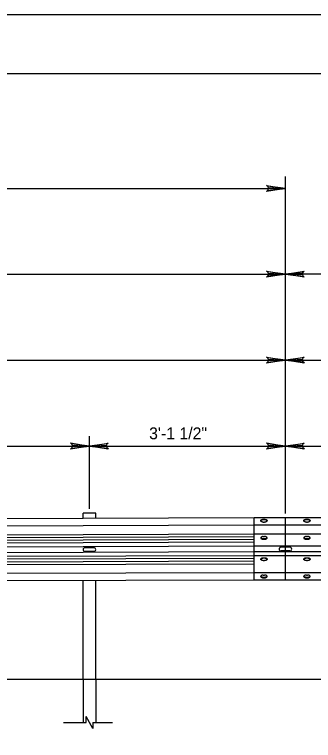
# Model space of a CAD drawing. Extents: x 637628 to 640188, y 298266 to 300751.
# Drawn here: x 639616.3 to 639692, y 299269.8 to 299453.6 of the extents above; entities that cross this region are included whole.
import ezdxf

# ---------------------------------------------------------------- set-up
doc = ezdxf.new("R2010")
doc.units = 0
for name, color, linetype in [('1', 7, 'Continuous'), ('2', 7, 'Continuous'), ('PLT-BNDY', 7, 'Continuous'), ('S-ABUT-CONC', 7, 'Continuous'), ('S-ANNO-CELL', 7, 'Continuous')]:
    doc.layers.add(name, color=color, linetype=linetype)

msp = doc.modelspace()

# ---------------------------------------------------------------- linework, layer by layer
at = {"layer": '1'}
msp.add_line((639676.99, 299310.39), (639676.99, 299326.12), dxfattribs=at)
msp.add_lwpolyline([(639945.52, 298874.58), (639945.52, 299438.55), (639159.55, 299438.55), (639159.55, 298874.58), (639945.52, 298874.58), (639945.52, 298900.93), (639745.53, 298900.93), (639745.53, 298965.61), (639945.52, 298965.61), (639945.52, 298994.57), (639745.53, 298994.57), (639745.53, 298874.58), (639824.33, 298874.58), (639824.33, 298900.93), (639824.33, 298874.58), (639901.33, 298874.58), (639901.33, 298900.93), (639901.33, 298888.62), (639945.52, 298888.62)], dxfattribs=at)
at = {"layer": '2'}
for points in [[(639680.4, 299410.12), (639680.57, 299409.79), (639684.94, 299409.55), (639680.4, 299410.12), (639680.17, 299410.32), (639684.94, 299409.55), (639680.58, 299409.33), (639680.42, 299409.01), (639684.94, 299409.55), (639680.17, 299408.79), (639680.42, 299409.01)], [(639680.4, 299388.41), (639680.57, 299388.08), (639684.94, 299387.84), (639680.4, 299388.41), (639680.17, 299388.61), (639684.94, 299387.84), (639680.58, 299387.62), (639680.42, 299387.3), (639684.94, 299387.84), (639680.17, 299387.08), (639680.42, 299387.3)], [(639689.48, 299387.27), (639689.31, 299387.6), (639684.94, 299387.84), (639689.48, 299387.27), (639689.72, 299387.07), (639684.94, 299387.84), (639689.31, 299388.05), (639689.47, 299388.38), (639684.94, 299387.84), (639689.72, 299388.6), (639689.47, 299388.38)], [(639680.4, 299366.65), (639680.57, 299366.32), (639684.94, 299366.09), (639680.4, 299366.65), (639680.17, 299366.85), (639684.94, 299366.09), (639680.58, 299365.87), (639680.42, 299365.54), (639684.94, 299366.09), (639680.17, 299365.32), (639680.42, 299365.54)], [(639689.48, 299365.52), (639689.31, 299365.85), (639684.94, 299366.09), (639689.48, 299365.52), (639689.72, 299365.32), (639684.94, 299366.09), (639689.31, 299366.3), (639689.47, 299366.63), (639684.94, 299366.09), (639689.72, 299366.85), (639689.47, 299366.63)], [(639630.74, 299344.9), (639630.91, 299344.57), (639635.28, 299344.33), (639630.74, 299344.9), (639630.51, 299345.1), (639635.28, 299344.33), (639630.92, 299344.12), (639630.76, 299343.79), (639635.28, 299344.33), (639630.51, 299343.57), (639630.76, 299343.79)], [(639639.82, 299343.76), (639639.65, 299344.09), (639635.28, 299344.33), (639639.82, 299343.76), (639640.06, 299343.56), (639635.28, 299344.33), (639639.65, 299344.55), (639639.81, 299344.87), (639635.28, 299344.33), (639640.06, 299345.09), (639639.81, 299344.87)], [(639680.4, 299344.9), (639680.57, 299344.57), (639684.94, 299344.33), (639680.4, 299344.9), (639680.17, 299345.1), (639684.94, 299344.33), (639680.58, 299344.12), (639680.42, 299343.79), (639684.94, 299344.33), (639680.17, 299343.57), (639680.42, 299343.79)], [(639689.48, 299343.76), (639689.31, 299344.09), (639684.94, 299344.33), (639689.48, 299343.76), (639689.72, 299343.56), (639684.94, 299344.33), (639689.31, 299344.55), (639689.47, 299344.87), (639684.94, 299344.33), (639689.72, 299345.09), (639689.47, 299344.87)]]:
    msp.add_lwpolyline(points, dxfattribs=at)
at = {"layer": 'PLT-BNDY'}
msp.add_lwpolyline([(639119.52, 299453.58), (639960.52, 299453.58), (639960.52, 298859.58), (639119.52, 298859.58)], close=True, dxfattribs=at)
at = {"layer": 'S-ABUT-CONC'}
for p, q in [((639684.94, 299327.27), (639684.94, 299412.56)), ((639287.66, 299409.55), (639684.94, 299409.55)), ((639486.3, 299387.84), (639684.94, 299387.84)), ((639899.46, 299387.84), (639684.94, 299387.84)), ((639486.3, 299366.09), (639684.94, 299366.09)), ((639684.94, 299366.09), (639833.71, 299366.09)), ((639635.28, 299328.4), (639635.28, 299346.82)), ((639535.96, 299344.33), (639635.28, 299344.33)), ((639635.28, 299344.33), (639684.94, 299344.33)), ((639684.94, 299344.33), (639734.6, 299344.33))]:
    msp.add_line(p, q, dxfattribs=at)
at = {"layer": 'S-ANNO-CELL'}
for p, q in [((639676.99, 299326.12), (639494.26, 299325.48)), ((639636.87, 299327.37), (639633.69, 299327.37)), ((639633.69, 299325.97), (639633.69, 299327.37)), ((639636.87, 299325.98), (639636.87, 299327.37)), ((639895.3, 299326.12), (639676.99, 299326.12)), ((639684.94, 299310.52), (639684.94, 299326.12)), ((639676.99, 299324.27), (639494.26, 299323.63)), ((639825.97, 299324.27), (639676.99, 299324.27)), ((639679.33, 299325.77), (639679.65, 299325.77)), ((639679.33, 299325.66), (639679.33, 299325.77)), ((639679.65, 299325.66), (639679.33, 299325.66)), ((639679.33, 299325.06), (639679.65, 299325.06)), ((639679.65, 299325.66), (639679.65, 299325.77)), ((639690.24, 299325.77), (639690.56, 299325.77)), ((639690.24, 299325.66), (639690.24, 299325.77)), ((639690.56, 299325.66), (639690.24, 299325.66)), ((639690.24, 299325.06), (639690.56, 299325.06)), ((639690.56, 299325.66), (639690.56, 299325.77)), ((639676.99, 299322.01), (639494.26, 299321.37)), ((639676.99, 299321.32), (639494.26, 299320.68)), ((639676.99, 299320.63), (639494.26, 299320)), ((639825.97, 299322.01), (639676.99, 299322.01)), ((639679.33, 299321.42), (639679.65, 299321.42)), ((639679.33, 299320.82), (639679.33, 299320.71)), ((639679.65, 299320.82), (639679.33, 299320.82)), ((639679.33, 299320.71), (639679.65, 299320.71)), ((639679.65, 299320.82), (639679.65, 299320.71)), ((639690.24, 299321.42), (639690.56, 299321.42)), ((639690.24, 299320.82), (639690.24, 299320.71)), ((639690.56, 299320.82), (639690.24, 299320.82)), ((639690.24, 299320.71), (639690.56, 299320.71)), ((639690.56, 299320.82), (639690.56, 299320.71)), ((639676.99, 299319.95), (639494.26, 299319.31)), ((639676.99, 299318.95), (639494.26, 299318.31)), ((639825.97, 299318.95), (639676.99, 299318.95)), ((639684.94, 299318.73), (639683.83, 299318.73)), ((639686.06, 299318.73), (639684.94, 299318.73)), ((639676.99, 299317.55), (639494.26, 299316.91)), ((639635.28, 299318.58), (639634.17, 299318.58)), ((639635.28, 299317.63), (639634.17, 299317.63)), ((639636.4, 299318.58), (639635.28, 299318.58)), ((639636.4, 299317.63), (639635.28, 299317.63)), ((639825.97, 299317.55), (639676.99, 299317.55)), ((639684.94, 299317.77), (639683.83, 299317.77)), ((639686.06, 299317.77), (639684.94, 299317.77)), ((639676.99, 299316.56), (639494.26, 299315.95)), ((639676.99, 299315.87), (639494.26, 299315.23)), ((639676.99, 299315.14), (639494.26, 299314.5)), ((639825.97, 299316.56), (639676.99, 299316.56)), ((639679.33, 299316.02), (639679.65, 299316.02)), ((639679.33, 299315.91), (639679.33, 299316.02)), ((639679.65, 299315.91), (639679.33, 299315.91)), ((639679.33, 299315.31), (639679.65, 299315.31)), ((639679.65, 299315.91), (639679.65, 299316.02)), ((639690.24, 299316.02), (639690.56, 299316.02)), ((639690.24, 299315.91), (639690.24, 299316.02)), ((639690.56, 299315.91), (639690.24, 299315.91)), ((639690.24, 299315.31), (639690.56, 299315.31)), ((639690.56, 299315.91), (639690.56, 299316.02)), ((639676.99, 299314.45), (639494.26, 299313.82)), ((639676.99, 299312.24), (639494.26, 299311.6)), ((639825.97, 299312.24), (639676.99, 299312.24)), ((639679.33, 299311.67), (639679.65, 299311.67)), ((639690.24, 299311.67), (639690.56, 299311.67)), ((639676.99, 299310.39), (639494.26, 299309.75)), ((639633.69, 299285.33), (639633.69, 299310.24)), ((639636.87, 299285.33), (639636.87, 299310.25)), ((639825.97, 299310.39), (639676.99, 299310.39)), ((639679.33, 299311.07), (639679.33, 299310.96)), ((639679.65, 299311.07), (639679.33, 299311.07)), ((639679.33, 299310.96), (639679.65, 299310.96)), ((639679.65, 299311.07), (639679.65, 299310.96)), ((639690.24, 299311.07), (639690.24, 299310.96)), ((639690.56, 299311.07), (639690.24, 299311.07)), ((639690.24, 299310.96), (639690.56, 299310.96)), ((639690.56, 299311.07), (639690.56, 299310.96)), ((639581.11, 299285.33), (639895.3, 299285.33)), ((639633.69, 299285.33), (639633.69, 299274.31)), ((639636.87, 299285.33), (639636.87, 299274.31)), ((639634.46, 299274.31), (639634.46, 299275.81)), ((639636.1, 299272.81), (639634.46, 299275.81)), ((639628.69, 299274.31), (639632.92, 299274.31)), ((639629.46, 299274.31), (639634.46, 299274.31)), ((639636.1, 299274.31), (639636.1, 299272.81)), ((639636.1, 299274.31), (639641.1, 299274.31))]:
    msp.add_line(p, q, dxfattribs=at)
for points in [[(639679.33, 299325.06), (639679.22, 299325.07), (639679.11, 299325.08), (639679.01, 299325.11), (639678.92, 299325.15), (639678.84, 299325.19), (639678.78, 299325.24), (639678.73, 299325.3), (639678.7, 299325.36), (639678.69, 299325.42), (639678.7, 299325.48), (639678.73, 299325.54), (639678.78, 299325.6), (639678.84, 299325.65), (639678.92, 299325.69), (639679.01, 299325.73), (639679.11, 299325.75), (639679.22, 299325.77), (639679.33, 299325.77)], [(639679.33, 299325.66), (639679.22, 299325.66), (639679.11, 299325.64), (639679.01, 299325.62), (639678.92, 299325.58), (639678.84, 299325.54), (639678.78, 299325.49), (639678.73, 299325.43), (639678.7, 299325.37), (639678.7, 299325.36)], [(639679.65, 299325.77), (639679.76, 299325.77), (639679.86, 299325.75), (639679.96, 299325.73), (639680.05, 299325.69), (639680.13, 299325.65), (639680.2, 299325.6), (639680.24, 299325.54), (639680.27, 299325.48), (639680.28, 299325.42), (639680.27, 299325.36), (639680.24, 299325.3), (639680.2, 299325.24), (639680.13, 299325.19), (639680.05, 299325.15), (639679.96, 299325.11), (639679.86, 299325.08), (639679.76, 299325.07), (639679.65, 299325.06)], [(639680.27, 299325.36), (639680.27, 299325.37), (639680.24, 299325.43), (639680.2, 299325.49), (639680.13, 299325.54), (639680.05, 299325.58), (639679.96, 299325.62), (639679.86, 299325.64), (639679.76, 299325.66), (639679.65, 299325.66)], [(639690.24, 299325.06), (639690.13, 299325.07), (639690.02, 299325.08), (639689.92, 299325.11), (639689.83, 299325.15), (639689.75, 299325.19), (639689.69, 299325.24), (639689.64, 299325.3), (639689.61, 299325.36), (639689.6, 299325.42), (639689.61, 299325.48), (639689.64, 299325.54), (639689.69, 299325.6), (639689.75, 299325.65), (639689.83, 299325.69), (639689.92, 299325.73), (639690.02, 299325.75), (639690.13, 299325.77), (639690.24, 299325.77)], [(639690.24, 299325.66), (639690.13, 299325.66), (639690.02, 299325.64), (639689.92, 299325.62), (639689.83, 299325.58), (639689.75, 299325.54), (639689.69, 299325.49), (639689.64, 299325.43), (639689.61, 299325.37), (639689.61, 299325.36)], [(639690.56, 299325.77), (639690.67, 299325.77), (639690.78, 299325.75), (639690.88, 299325.73), (639690.97, 299325.69), (639691.05, 299325.65), (639691.11, 299325.6), (639691.16, 299325.54), (639691.19, 299325.48), (639691.2, 299325.42), (639691.19, 299325.36), (639691.16, 299325.3), (639691.11, 299325.24), (639691.05, 299325.19), (639690.97, 299325.15), (639690.88, 299325.11), (639690.78, 299325.08), (639690.67, 299325.07), (639690.56, 299325.06)], [(639691.19, 299325.36), (639691.19, 299325.37), (639691.16, 299325.43), (639691.11, 299325.49), (639691.05, 299325.54), (639690.97, 299325.58), (639690.88, 299325.62), (639690.78, 299325.64), (639690.67, 299325.66), (639690.56, 299325.66)], [(639679.33, 299321.42), (639679.22, 299321.42), (639679.11, 299321.4), (639679.01, 299321.37), (639678.92, 299321.34), (639678.84, 299321.29), (639678.78, 299321.24), (639678.73, 299321.19), (639678.7, 299321.13), (639678.69, 299321.06), (639678.7, 299321), (639678.73, 299320.94), (639678.78, 299320.89), (639678.84, 299320.84), (639678.92, 299320.79), (639679.01, 299320.76), (639679.11, 299320.73), (639679.22, 299320.71), (639679.33, 299320.71)], [(639679.33, 299320.82), (639679.22, 299320.82), (639679.11, 299320.84), (639679.01, 299320.87), (639678.92, 299320.9), (639678.84, 299320.95), (639678.78, 299321), (639678.73, 299321.05), (639678.7, 299321.11), (639678.7, 299321.12)], [(639679.65, 299320.71), (639679.76, 299320.71), (639679.86, 299320.73), (639679.96, 299320.76), (639680.05, 299320.79), (639680.13, 299320.84), (639680.2, 299320.89), (639680.24, 299320.94), (639680.27, 299321), (639680.28, 299321.06), (639680.27, 299321.13), (639680.24, 299321.19), (639680.2, 299321.24), (639680.13, 299321.29), (639680.05, 299321.34), (639679.96, 299321.37), (639679.86, 299321.4), (639679.76, 299321.42), (639679.65, 299321.42)], [(639680.27, 299321.12), (639680.27, 299321.11), (639680.24, 299321.05), (639680.2, 299321), (639680.13, 299320.95), (639680.05, 299320.9), (639679.96, 299320.87), (639679.86, 299320.84), (639679.76, 299320.82), (639679.65, 299320.82)], [(639690.24, 299321.42), (639690.13, 299321.42), (639690.02, 299321.4), (639689.92, 299321.37), (639689.83, 299321.34), (639689.75, 299321.29), (639689.69, 299321.24), (639689.64, 299321.19), (639689.61, 299321.13), (639689.6, 299321.06), (639689.61, 299321), (639689.64, 299320.94), (639689.69, 299320.89), (639689.75, 299320.84), (639689.83, 299320.79), (639689.92, 299320.76), (639690.02, 299320.73), (639690.13, 299320.71), (639690.24, 299320.71)], [(639690.24, 299320.82), (639690.13, 299320.82), (639690.02, 299320.84), (639689.92, 299320.87), (639689.83, 299320.9), (639689.75, 299320.95), (639689.69, 299321), (639689.64, 299321.05), (639689.61, 299321.11), (639689.61, 299321.12)], [(639690.56, 299320.71), (639690.67, 299320.71), (639690.78, 299320.73), (639690.88, 299320.76), (639690.97, 299320.79), (639691.05, 299320.84), (639691.11, 299320.89), (639691.16, 299320.94), (639691.19, 299321), (639691.2, 299321.06), (639691.19, 299321.13), (639691.16, 299321.19), (639691.11, 299321.24), (639691.05, 299321.29), (639690.97, 299321.34), (639690.88, 299321.37), (639690.78, 299321.4), (639690.67, 299321.42), (639690.56, 299321.42)], [(639691.19, 299321.12), (639691.19, 299321.11), (639691.16, 299321.05), (639691.11, 299321), (639691.05, 299320.95), (639690.97, 299320.9), (639690.88, 299320.87), (639690.78, 299320.84), (639690.67, 299320.82), (639690.56, 299320.82)], [(639679.33, 299315.31), (639679.22, 299315.32), (639679.11, 299315.33), (639679.01, 299315.36), (639678.92, 299315.4), (639678.84, 299315.44), (639678.78, 299315.49), (639678.73, 299315.55), (639678.7, 299315.61), (639678.69, 299315.67), (639678.7, 299315.73), (639678.73, 299315.79), (639678.78, 299315.85), (639678.84, 299315.9), (639678.92, 299315.94), (639679.01, 299315.98), (639679.11, 299316), (639679.22, 299316.02), (639679.33, 299316.02)], [(639679.33, 299315.91), (639679.22, 299315.91), (639679.11, 299315.89), (639679.01, 299315.87), (639678.92, 299315.83), (639678.84, 299315.79), (639678.78, 299315.74), (639678.73, 299315.68), (639678.7, 299315.62), (639678.7, 299315.61)], [(639679.65, 299316.02), (639679.76, 299316.02), (639679.86, 299316), (639679.96, 299315.98), (639680.05, 299315.94), (639680.13, 299315.9), (639680.2, 299315.85), (639680.24, 299315.79), (639680.27, 299315.73), (639680.28, 299315.67), (639680.27, 299315.61), (639680.24, 299315.55), (639680.2, 299315.49), (639680.13, 299315.44), (639680.05, 299315.4), (639679.96, 299315.36), (639679.86, 299315.33), (639679.76, 299315.32), (639679.65, 299315.31)], [(639680.27, 299315.61), (639680.27, 299315.62), (639680.24, 299315.68), (639680.2, 299315.74), (639680.13, 299315.79), (639680.05, 299315.83), (639679.96, 299315.87), (639679.86, 299315.89), (639679.76, 299315.91), (639679.65, 299315.91)], [(639690.24, 299315.31), (639690.13, 299315.32), (639690.02, 299315.33), (639689.92, 299315.36), (639689.83, 299315.4), (639689.75, 299315.44), (639689.69, 299315.49), (639689.64, 299315.55), (639689.61, 299315.61), (639689.6, 299315.67), (639689.61, 299315.73), (639689.64, 299315.79), (639689.69, 299315.85), (639689.75, 299315.9), (639689.83, 299315.94), (639689.92, 299315.98), (639690.02, 299316), (639690.13, 299316.02), (639690.24, 299316.02)], [(639690.24, 299315.91), (639690.13, 299315.91), (639690.02, 299315.89), (639689.92, 299315.87), (639689.83, 299315.83), (639689.75, 299315.79), (639689.69, 299315.74), (639689.64, 299315.68), (639689.61, 299315.62), (639689.61, 299315.61)], [(639690.56, 299316.02), (639690.67, 299316.02), (639690.78, 299316), (639690.88, 299315.98), (639690.97, 299315.94), (639691.05, 299315.9), (639691.11, 299315.85), (639691.16, 299315.79), (639691.19, 299315.73), (639691.2, 299315.67), (639691.19, 299315.61), (639691.16, 299315.55), (639691.11, 299315.49), (639691.05, 299315.44), (639690.97, 299315.4), (639690.88, 299315.36), (639690.78, 299315.33), (639690.67, 299315.32), (639690.56, 299315.31)], [(639691.19, 299315.61), (639691.19, 299315.62), (639691.16, 299315.68), (639691.11, 299315.74), (639691.05, 299315.79), (639690.97, 299315.83), (639690.88, 299315.87), (639690.78, 299315.89), (639690.67, 299315.91), (639690.56, 299315.91)], [(639679.33, 299311.67), (639679.22, 299311.67), (639679.11, 299311.65), (639679.01, 299311.62), (639678.92, 299311.59), (639678.84, 299311.54), (639678.78, 299311.49), (639678.73, 299311.44), (639678.7, 299311.38), (639678.69, 299311.31), (639678.7, 299311.25), (639678.73, 299311.19), (639678.78, 299311.14), (639678.84, 299311.09), (639678.92, 299311.04), (639679.01, 299311.01), (639679.11, 299310.98), (639679.22, 299310.96), (639679.33, 299310.96)], [(639679.33, 299311.07), (639679.22, 299311.07), (639679.11, 299311.09), (639679.01, 299311.12), (639678.92, 299311.15), (639678.84, 299311.2), (639678.78, 299311.25), (639678.73, 299311.3), (639678.7, 299311.36), (639678.7, 299311.37)], [(639679.65, 299310.96), (639679.76, 299310.96), (639679.86, 299310.98), (639679.96, 299311.01), (639680.05, 299311.04), (639680.13, 299311.09), (639680.2, 299311.14), (639680.24, 299311.19), (639680.27, 299311.25), (639680.28, 299311.31), (639680.27, 299311.38), (639680.24, 299311.44), (639680.2, 299311.49), (639680.13, 299311.54), (639680.05, 299311.59), (639679.96, 299311.62), (639679.86, 299311.65), (639679.76, 299311.67), (639679.65, 299311.67)], [(639680.27, 299311.37), (639680.27, 299311.36), (639680.24, 299311.3), (639680.2, 299311.25), (639680.13, 299311.2), (639680.05, 299311.15), (639679.96, 299311.12), (639679.86, 299311.09), (639679.76, 299311.07), (639679.65, 299311.07)], [(639690.24, 299311.67), (639690.13, 299311.67), (639690.02, 299311.65), (639689.92, 299311.62), (639689.83, 299311.59), (639689.75, 299311.54), (639689.69, 299311.49), (639689.64, 299311.44), (639689.61, 299311.38), (639689.6, 299311.31), (639689.61, 299311.25), (639689.64, 299311.19), (639689.69, 299311.14), (639689.75, 299311.09), (639689.83, 299311.04), (639689.92, 299311.01), (639690.02, 299310.98), (639690.13, 299310.96), (639690.24, 299310.96)], [(639690.24, 299311.07), (639690.13, 299311.07), (639690.02, 299311.09), (639689.92, 299311.12), (639689.83, 299311.15), (639689.75, 299311.2), (639689.69, 299311.25), (639689.64, 299311.3), (639689.61, 299311.36), (639689.61, 299311.37)], [(639690.56, 299310.96), (639690.67, 299310.96), (639690.78, 299310.98), (639690.88, 299311.01), (639690.97, 299311.04), (639691.05, 299311.09), (639691.11, 299311.14), (639691.16, 299311.19), (639691.19, 299311.25), (639691.2, 299311.31), (639691.19, 299311.38), (639691.16, 299311.44), (639691.11, 299311.49), (639691.05, 299311.54), (639690.97, 299311.59), (639690.88, 299311.62), (639690.78, 299311.65), (639690.67, 299311.67), (639690.56, 299311.67)], [(639691.19, 299311.37), (639691.19, 299311.36), (639691.16, 299311.3), (639691.11, 299311.25), (639691.05, 299311.2), (639690.97, 299311.15), (639690.88, 299311.12), (639690.78, 299311.09), (639690.67, 299311.07), (639690.56, 299311.07)]]:
    msp.add_lwpolyline(points, dxfattribs=at)
for centre, start, end in [((639683.83, 299318.25), 90, 270), ((639686.06, 299318.25), 270, 90), ((639634.17, 299318.1), 90, 270), ((639636.4, 299318.1), 270, 90)]:
    msp.add_arc(centre, 0.478, start, end, dxfattribs=at)

# ---------------------------------------------------------------- texts
at = {"layer": 'S-ABUT-CONC'}
msp.add_text('3\'-1 1/2"', height=3, dxfattribs=at).set_placement((639650.4, 299346.04))

doc.saveas('drawing.dxf')
